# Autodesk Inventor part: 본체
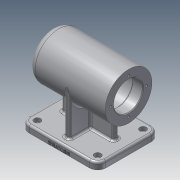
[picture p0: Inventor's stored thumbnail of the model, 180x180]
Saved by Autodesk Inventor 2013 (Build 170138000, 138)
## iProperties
Created: 2020-10
Part Number: 본체
Material: 알루미늄 6061
Document SubType Name: Modeling
Designer: user
Density: 2.71 g/cm^3
Mass: 1030.08 g
Surface Area: 757.984 cm^2
Volume: 380.102 cm^3
Author: user
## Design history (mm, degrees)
sketch "스케치1"
  geometry: C1 r 34 at (0, 0); 1 further point
  constraints: 1 centre point, 1 coincident
  dimensions: "d0" = 68 diameter of C1
extrude "돌출1" new body sketch "스케치1" distance "d1" = 112; taper "d2" = 0 deg
node "작업 평면1"
sketch "스케치2"
  geometry: L1 (45, 112)-(-45, 112); L2 (-45, 112)-(-45, 0); L3 (-45, 0)-(45, 0); L4 (45, 0)-(45, 112); L5 (45, 112)-(-45, 0); L6 (-45, 112)-(45, 0); 3 further points
  constraints: 12 end point, 3 midpoint, 2 parallel, 1 coincident, 1 horizontal, 1 perpendicular
  dimensions: "d4" = 90 distance of L3.end L2.end; "d5" = 112 distance of L2.end L1.end
extrude "돌출2" join sketch "스케치2" distance "d6" = 10; taper "d7" = 0 deg
sketch "스케치3"
  geometry: L1 (-45, -112)-(45, -112) reference; L2 (45, 0)-(-45, 0) reference; L3 (-45, 0)-(-45, -112) reference; L4 (-4, -94)-(4, -94); L5 (4, -94)-(4, -18); L6 (4, -18)-(-4, -18); L7 (-4, -18)-(-4, -94); L8 (-4, -94)-(4, -18); L9 (4, -94)-(-4, -18); 2 further points
  constraints: 12 end point, 2 midpoint, 2 parallel, 1 horizontal, 1 perpendicular
  dimensions: "d8" = 8 distance of L5.end L6.end; "d10" = 18 distance between parallel lines of L2 L6; "d11" = 18 distance between parallel lines of L1 L4; "d12" = 45 distance from line of point (0, -56) L3
extrude "돌출3" join sketch "스케치3" stored distance "d13" = 10; taper "d14" = 0 deg
sketch "스케치4"
  geometry: L1 (45, 0)-(-45, 0) reference; L2 (-34, -52)-(34, -52); L3 (34, -52)-(34, -60); L4 (34, -60)-(-34, -60); L5 (-34, -60)-(-34, -52); L6 (-34, -52)-(34, -60); L7 (34, -52)-(-34, -60); 4 further points
  constraints: 12 end point, 4 midpoint, 2 parallel, 1 horizontal, 1 perpendicular, 1 vertical alignment
  dimensions: "d15" = 8 distance of L4.end L2.start; "d17" = 68 distance of L3.end L4.end; "d18" = 56 distance from line of L1 point (0, -56)
extrude "돌출4" join sketch "스케치4" stored distance "d19" = 10; taper "d20" = 0 deg
sketch "스케치5"
  geometry: L1 (34, 112)-(34, 0) reference; L2 (34, 0)-(-34, 0) reference; L3 (-34, 0)-(-34, 18) reference; L4 (-34, 18)-(-64, 18) reference; L5 (-64, 18)-(-64, 0) reference; L6 (-64, 0)-(-74, 0) reference; L7 (-74, 0)-(-74, 112) reference; L8 (-74, 112)-(-64, 112) reference; L9 (-64, 112)-(-64, 94) reference; L10 (-64, 94)-(-34, 94) reference; L11 (-34, 94)-(-34, 112) reference; L12 (-34, 112)-(34, 112) reference; L13 (0, 112)-(0, 0); L14 (0, 0)-(21, 0); L15 (21, 0)-(21, 15); L16 (21, 15)-(24, 15); L17 (24, 15)-(24, 69); L18 (24, 69)-(21, 69); L19 (21, 69)-(21, 81); L20 (21, 81)-(17.5, 81); L21 (17.5, 81)-(17.5, 99); L22 (17.5, 99)-(16, 99); L23 (16, 99)-(16, 103); L24 (16, 103)-(10.5, 103); L25 (10.5, 103)-(10.5, 106); L26 (10.5, 106)-(0, 106)
  constraints: 28 end point, 8 parallel, 4 perpendicular, 2 point on line, 1 collinear, 1 midpoint
  dimensions: "d21" = 15 distance of L14.end L15.end; "d23" = 54 distance of L16.end L17.end; "d24" = 12 distance of L18.end L19.end; "d25" = 18 distance of L20.end L21.end; "d26" = 4 distance of L22.end L23.end; "d27" = 3 distance of L24.end L25.end; "d28" = 42 diameter of L15 L13; "d29" = 48 diameter of L17 L13; "d30" = 42 diameter of L19 L13; "d31" = 35 diameter of L21 L13; "d32" = 32 diameter of L23 L13; "d33" = 21 diameter of L25 L13
revolve "회전1" sketch "스케치5" stored, may be unused: angle "d34" = 90 deg
fillet "모깎기1" dims "d35" = 3
fillet "모깎기2" dims "d36" = 0.3
fillet "모깎기3" dims "d37" = 3
chamfer "모따기1" distance "d38" = 1; stored, may be unused: second distance "d39" = 2, angle "d40" = 45 deg
sketch "스케치6" dims "d41" = 52
  geometry: C1 r 34 at (0, 0) reference; C2 r 22 at (0, 0) reference; 2 further points
  constraints: 3 coincident, 2 vertical alignment, 2 other
hole "구멍1" sketch "스케치6" at (0, 26) diameter "d42" = 3.242; stored, may be unused: countersink angle "d46" = 90 deg, drill point angle "d48" = 118 deg; dims "d43" = 8, "d44" = 4, "d45" = 2, "d47" = 11
sketch "스케치7"
  geometry: L1 (0, 0)-(112, 0) reference; L2 (112, 0)-(112, 10) reference; 2 further points
  constraints: 1 other
  dimensions: "d52" = 56 distance from line of L2 point (56, 3); "d53" = 3 distance from line of L1 point (56, 3)
feature "엠보싱1" sketch "스케치7" dims "d1" = 112, "d2" = 0, "d54" = 0.5, "d55" = 0
fillet "모깎기4" dims "d56" = 12
sketch "스케치8"
  geometry: A1 r 12 centre (-33, -100) between (-45, -100) and (-33, -112) reference; A2 r 12 centre (33, -100) between (33, -112) and (45, -100) reference; A3 r 12 centre (33, -12) between (45, -12) and (33, 0) reference; A4 r 12 centre (-33, -12) between (-33, 0) and (-45, -12) reference; 5 further points
  constraints: 4 coincident
hole "구멍2" sketch "스케치8" at (-33, -100), (33, -100), (33, -12), (-33, -12) diameter "d57" = 5.5; stored, may be unused: countersink angle "d61" = 90 deg, drill point angle "d63" = 118 deg; dims "d58" = 8, "d59" = 9.5, "d60" = 5.4, "d62" = 11
fillet "모깎기5" dims "d64" = 10
fillet "모깎기6" dims "d65" = 3
fillet "모깎기7" dims "d66" = 3
fillet "모깎기8" dims "d67" = 3
fillet "모깎기9" dims "d68" = 3
fillet "모깎기10" dims "d69" = 3
node "솔리드1"
pattern_circular "원형 패턴1" dims angle "d50" = 360 deg
node "절단 모서리 투영1"
other parameters: "d3" = -74
